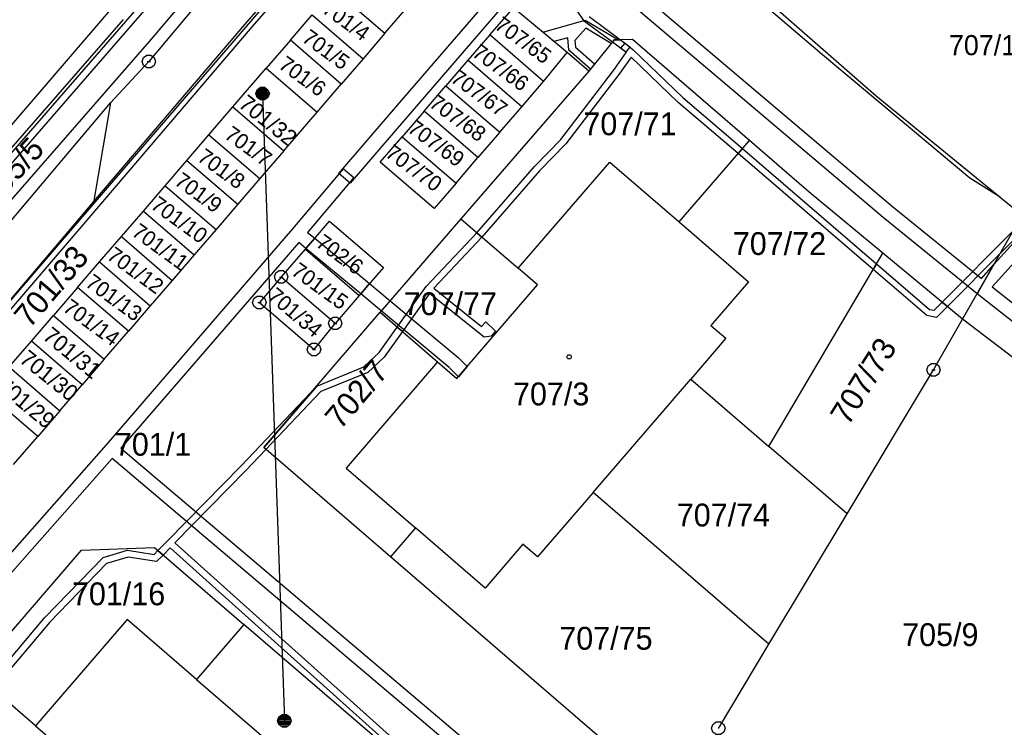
# Model space of a CAD drawing. Extents: x -759060 to -757386, y -1172273 to -1170948.
# Drawn here: x -757830.3 to -757756.9, y -1171110.1 to -1171057.4 of the extents above; entities that cross this region are included whole.
import ezdxf

# ---------------------------------------------------------------- set-up
doc = ezdxf.new("R2010")
doc.units = 0
for name, color, linetype in [('Vrstva 1', 7, 'Continuous'), ('Vrstva 12', 7, 'Continuous'), ('Vrstva 13', 7, 'Continuous'), ('Vrstva 2', 7, 'Continuous'), ('Vrstva 5', 7, 'Continuous'), ('Vrstva 6', 7, 'Continuous'), ('Vrstva 8', 7, 'Continuous')]:
    doc.layers.add(name, color=color, linetype=linetype)

msp = doc.modelspace()

# ---------------------------------------------------------------- linework, layer by layer
at = {"layer": 'Vrstva 1'}
for p, q in [((-757804.36, -1171041.02), (-757820.7, -1171060.56)), ((-757844.19, -1171080.69), (-757811.7, -1171042.9)), ((-757824.84, -1171071.19), (-757804.1, -1171047.12)), ((-757806.89, -1171055.18), (-757803.1, -1171058.44)), ((-757803.1, -1171058.44), (-757801.46, -1171056.55)), ((-757795.29, -1171058.57), (-757793.51, -1171056.55)), ((-757789.52, -1171059.89), (-757793.51, -1171056.55)), ((-757774.02, -1171056.52), (-757766.48, -1171063.11)), ((-757810.15, -1171058.97), (-757808.52, -1171057.07)), ((-757808.52, -1171057.07), (-757804.73, -1171060.34)), ((-757803.1, -1171058.44), (-757804.73, -1171060.34)), ((-757810.15, -1171058.97), (-757811.95, -1171061.05)), ((-757806.37, -1171062.23), (-757810.15, -1171058.97)), ((-757795.29, -1171058.57), (-757796.92, -1171060.46)), ((-757791.28, -1171062.03), (-757795.29, -1171058.57)), ((-757786.02, -1171058.94), (-757787.91, -1171061.26)), ((-757784.66, -1171058.91), (-757786.02, -1171058.94)), ((-757775.94, -1171066.44), (-757784.66, -1171058.91)), ((-757791.28, -1171062.03), (-757789.52, -1171059.89)), ((-757787.91, -1171061.26), (-757789.52, -1171059.89)), ((-757820.7, -1171060.56), (-757823.57, -1171063.62)), ((-757804.73, -1171060.34), (-757806.37, -1171062.23)), ((-757796.92, -1171060.46), (-757798.56, -1171062.36)), ((-757792.91, -1171063.92), (-757796.92, -1171060.46)), ((-757814.43, -1171063.93), (-757811.95, -1171061.05)), ((-757811.95, -1171061.05), (-757808.16, -1171064.31)), ((-757787.91, -1171061.26), (-757797.45, -1171072.26)), ((-757792.91, -1171063.92), (-757791.28, -1171062.03)), ((-757808.16, -1171064.31), (-757806.37, -1171062.23)), ((-757800.18, -1171064.25), (-757798.56, -1171062.36)), ((-757798.56, -1171062.36), (-757794.54, -1171065.82)), ((-757859.93, -1171106.73), (-757823.57, -1171063.62)), ((-757823.57, -1171063.62), (-757824.84, -1171071.19)), ((-757766.48, -1171063.11), (-757755.61, -1171071.99)), ((-757816.22, -1171066.01), (-757814.43, -1171063.93)), ((-757814.43, -1171063.93), (-757810.64, -1171067.19)), ((-757810.64, -1171067.19), (-757808.16, -1171064.31)), ((-757800.18, -1171064.25), (-757801.82, -1171066.15)), ((-757796.17, -1171067.71), (-757800.18, -1171064.25)), ((-757794.54, -1171065.82), (-757792.91, -1171063.92)), ((-757794.54, -1171065.82), (-757796.17, -1171067.71)), ((-757817.86, -1171067.91), (-757816.22, -1171066.01)), ((-757816.22, -1171066.01), (-757812.43, -1171069.27)), ((-757803.45, -1171068.04), (-757801.82, -1171066.15)), ((-757801.82, -1171066.15), (-757797.8, -1171069.6)), ((-757781.18, -1171072.49), (-757775.94, -1171066.44)), ((-757771.48, -1171070.29), (-757775.94, -1171066.44)), ((-757810.64, -1171067.19), (-757812.43, -1171069.27)), ((-757819.48, -1171069.8), (-757817.86, -1171067.91)), ((-757817.86, -1171067.91), (-757814.06, -1171071.17)), ((-757799.43, -1171071.5), (-757803.45, -1171068.04)), ((-757797.8, -1171069.6), (-757796.17, -1171067.71)), ((-757793.17, -1171075.95), (-757786.35, -1171068.04)), ((-757786.35, -1171068.04), (-757781.18, -1171072.49)), ((-757812.43, -1171069.27), (-757814.06, -1171071.17)), ((-757821.11, -1171071.69), (-757819.48, -1171069.8)), ((-757819.48, -1171069.8), (-757815.69, -1171073.06)), ((-757797.8, -1171069.6), (-757799.43, -1171071.5)), ((-757765.99, -1171074.83), (-757771.48, -1171070.29)), ((-757835.44, -1171083.49), (-757824.84, -1171071.19)), ((-757822.75, -1171073.59), (-757821.11, -1171071.69)), ((-757821.11, -1171071.69), (-757817.33, -1171074.96)), ((-757814.06, -1171071.17), (-757815.69, -1171073.06)), ((-757809.03, -1171074.52), (-757807.23, -1171072.43)), ((-757807.23, -1171072.43), (-757803.22, -1171075.89)), ((-757797.45, -1171072.26), (-757803.46, -1171079.23)), ((-757797.45, -1171072.26), (-757793.17, -1171075.95)), ((-757760.04, -1171079.74), (-757755.61, -1171071.99)), ((-757815.69, -1171073.06), (-757817.33, -1171074.96)), ((-757781.18, -1171072.49), (-757775.99, -1171076.96)), ((-757824.38, -1171075.48), (-757822.75, -1171073.59)), ((-757822.75, -1171073.59), (-757818.96, -1171076.85)), ((-757810.83, -1171076.6), (-757809.03, -1171074.52)), ((-757809.03, -1171074.52), (-757805.02, -1171077.98)), ((-757817.33, -1171074.96), (-757818.96, -1171076.85)), ((-757774.48, -1171089.22), (-757765.99, -1171074.83)), ((-757760.04, -1171079.74), (-757765.99, -1171074.83)), ((-757826.01, -1171077.38), (-757824.38, -1171075.48)), ((-757824.38, -1171075.48), (-757820.6, -1171078.75)), ((-757803.22, -1171075.89), (-757805.02, -1171077.98)), ((-757791.73, -1171077.19), (-757793.17, -1171075.95)), ((-757818.96, -1171076.85), (-757820.6, -1171078.75)), ((-757810.83, -1171076.6), (-757812.46, -1171078.5)), ((-757806.81, -1171080.06), (-757810.83, -1171076.6)), ((-757826.01, -1171077.38), (-757827.81, -1171079.46)), ((-757822.22, -1171080.64), (-757826.01, -1171077.38)), ((-757797.74, -1171084.16), (-757791.73, -1171077.19)), ((-757775.99, -1171076.96), (-757778.8, -1171080.22)), ((-757805.02, -1171077.98), (-757806.81, -1171080.06)), ((-757820.6, -1171078.75), (-757822.22, -1171080.64)), ((-757812.46, -1171078.5), (-757808.39, -1171082)), ((-757829.46, -1171081.38), (-757827.81, -1171079.46)), ((-757827.81, -1171079.46), (-757824.02, -1171082.72)), ((-757812.14, -1171089.31), (-757803.46, -1171079.23)), ((-757803.46, -1171079.23), (-757799.18, -1171082.92)), ((-757762.21, -1171083.52), (-757760.04, -1171079.74)), ((-757752.84, -1171085.25), (-757760.04, -1171079.74)), ((-757808.39, -1171082), (-757806.81, -1171080.06)), ((-757778.8, -1171080.22), (-757777.7, -1171081.16)), ((-757824.02, -1171082.72), (-757822.22, -1171080.64)), ((-757777.7, -1171081.16), (-757780.31, -1171084.2)), ((-757831.12, -1171083.3), (-757829.46, -1171081.38)), ((-757825.67, -1171084.64), (-757829.46, -1171081.38)), ((-757824.02, -1171082.72), (-757825.67, -1171084.64)), ((-757831.12, -1171083.3), (-757827.33, -1171086.56)), ((-757799.18, -1171082.92), (-757806, -1171090.84)), ((-757799.18, -1171082.92), (-757797.74, -1171084.16)), ((-757787.59, -1171092.64), (-757780.31, -1171084.2)), ((-757780.31, -1171084.2), (-757774.48, -1171089.22)), ((-757768.64, -1171094.23), (-757762.21, -1171083.52)), ((-757827.33, -1171086.56), (-757825.67, -1171084.64)), ((-757828.98, -1171088.48), (-757832.77, -1171085.22)), ((-757827.33, -1171086.56), (-757828.98, -1171088.48)), ((-757830.78, -1171090.57), (-757828.98, -1171088.48)), ((-757802.69, -1171097.45), (-757812.14, -1171089.31)), ((-757768.64, -1171094.23), (-757774.48, -1171089.22)), ((-757806, -1171090.84), (-757800.83, -1171095.29)), ((-757787.59, -1171092.64), (-757791.73, -1171097.45)), ((-757774.48, -1171103.94), (-757787.59, -1171092.64)), ((-757774.48, -1171103.94), (-757768.64, -1171094.23)), ((-757800.83, -1171095.29), (-757802.69, -1171097.45)), ((-757795.64, -1171099.77), (-757800.83, -1171095.29)), ((-757792.83, -1171096.51), (-757795.64, -1171099.77)), ((-757791.73, -1171097.45), (-757792.83, -1171096.51)), ((-757833.65, -1171106.15), (-757825.72, -1171096.95)), ((-757825.72, -1171096.95), (-757820.27, -1171096.76)), ((-757820.27, -1171096.76), (-757813.62, -1171102.48)), ((-757781.84, -1171115.41), (-757802.69, -1171097.45)), ((-757822.32, -1171102.12), (-757829.14, -1171110.04)), ((-757817.15, -1171106.57), (-757822.32, -1171102.12)), ((-757813.62, -1171102.48), (-757817.15, -1171106.57)), ((-757803.54, -1171111.16), (-757813.62, -1171102.48)), ((-757778.25, -1171110.22), (-757774.48, -1171103.94)), ((-757829.14, -1171110.04), (-757833.65, -1171106.15)), ((-757817.15, -1171106.57), (-757811.96, -1171111.05)), ((-757829.14, -1171110.04), (-757827.7, -1171111.28))]:
    msp.add_line(p, q, dxfattribs=at)
at = {"layer": 'Vrstva 12'}
for p, q in [((-757793.17, -1171075.95), (-757786.35, -1171068.04)), ((-757786.35, -1171068.04), (-757781.18, -1171072.49)), ((-757781.18, -1171072.49), (-757775.99, -1171076.96)), ((-757791.73, -1171077.19), (-757793.17, -1171075.95)), ((-757797.74, -1171084.16), (-757791.73, -1171077.19)), ((-757775.99, -1171076.96), (-757778.8, -1171080.22)), ((-757778.8, -1171080.22), (-757777.7, -1171081.16)), ((-757777.7, -1171081.16), (-757780.31, -1171084.2)), ((-757799.18, -1171082.92), (-757806, -1171090.84)), ((-757799.18, -1171082.92), (-757797.74, -1171084.16)), ((-757787.59, -1171092.64), (-757780.31, -1171084.2)), ((-757806, -1171090.84), (-757800.83, -1171095.29)), ((-757787.59, -1171092.64), (-757791.73, -1171097.45)), ((-757795.64, -1171099.77), (-757800.83, -1171095.29)), ((-757792.83, -1171096.51), (-757795.64, -1171099.77)), ((-757791.73, -1171097.45), (-757792.83, -1171096.51)), ((-757822.32, -1171102.12), (-757829.14, -1171110.04)), ((-757817.15, -1171106.57), (-757822.32, -1171102.12)), ((-757817.15, -1171106.57), (-757811.96, -1171111.05)), ((-757829.14, -1171110.04), (-757827.7, -1171111.28))]:
    msp.add_line(p, q, dxfattribs=at)
at = {"layer": 'Vrstva 13'}
for p, q in [((-757793.28, -1171026.85), (-757820.69, -1171059.05)), ((-757813.39, -1171057.63), (-757804.06, -1171046.81)), ((-757804, -1171047.54), (-757813.01, -1171057.95)), ((-757802.17, -1171063.81), (-757790.75, -1171050.57)), ((-757790.27, -1171051.7), (-757802.35, -1171065.71)), ((-757770.48, -1171060.06), (-757778.23, -1171053.45)), ((-757784.32, -1171055.22), (-757765.27, -1171071.34)), ((-757765.97, -1171072.18), (-757785.02, -1171056.06)), ((-757842.11, -1171080.2), (-757821.43, -1171056.42)), ((-757821.05, -1171056.74), (-757841.71, -1171080.5)), ((-757788.23, -1171057.56), (-757788.8, -1171056.72)), ((-757774.02, -1171056.52), (-757766.48, -1171063.11)), ((-757855.95, -1171095.7), (-757822.59, -1171057.41)), ((-757824.81, -1171070.98), (-757813.39, -1171057.63)), ((-757791.34, -1171058.37), (-757788.18, -1171057.46)), ((-757786.15, -1171059.1), (-757788.23, -1171057.56)), ((-757788.18, -1171057.46), (-757785.69, -1171058.93)), ((-757787.87, -1171057.2), (-757785.54, -1171058.93)), ((-757813.01, -1171057.95), (-757825.9, -1171073.03)), ((-757790.52, -1171059.05), (-757791.34, -1171058.37)), ((-757788.14, -1171058.07), (-757788.94, -1171058.98)), ((-757786.23, -1171059.2), (-757788.14, -1171058.07)), ((-757820.69, -1171059.05), (-757854.07, -1171097.34)), ((-757789.46, -1171058.79), (-757790.52, -1171059.05)), ((-757789.39, -1171059.71), (-757789.46, -1171058.79)), ((-757788.94, -1171058.98), (-757788.91, -1171059.47)), ((-757786.15, -1171059.1), (-757786.23, -1171059.2)), ((-757786.02, -1171058.94), (-757786.15, -1171059.1)), ((-757786.15, -1171059.1), (-757786.02, -1171058.94)), ((-757786.02, -1171058.94), (-757786.15, -1171059.1)), ((-757785.14, -1171059.85), (-757786.15, -1171059.1)), ((-757785.54, -1171058.93), (-757786.02, -1171058.94)), ((-757786.02, -1171058.94), (-757785.54, -1171058.93)), ((-757785.69, -1171058.93), (-757786.02, -1171058.94)), ((-757785.54, -1171058.93), (-757784.84, -1171059.45)), ((-757785.52, -1171059.56), (-757785.2, -1171059.18)), ((-757785.2, -1171059.18), (-757784.63, -1171059.66)), ((-757787.78, -1171061.11), (-757789.39, -1171059.71)), ((-757788.91, -1171059.47), (-757787.47, -1171060.72)), ((-757786, -1171061.12), (-757785.13, -1171059.89)), ((-757785.13, -1171059.89), (-757785.52, -1171059.56)), ((-757784.84, -1171059.45), (-757785.14, -1171059.85)), ((-757784.63, -1171059.66), (-757780.9, -1171063.23)), ((-757784.76, -1171060.23), (-757785.6, -1171061.42)), ((-757781.24, -1171063.59), (-757784.76, -1171060.23)), ((-757759.51, -1171069.25), (-757770.48, -1171060.06)), ((-757790, -1171066.37), (-757786, -1171061.12)), ((-757785.6, -1171061.42), (-757789.62, -1171066.69)), ((-757787.47, -1171060.72), (-757787.78, -1171061.11)), ((-757776.78, -1171067.41), (-757781.24, -1171063.59)), ((-757780.9, -1171063.23), (-757776.46, -1171067.04)), ((-757766.48, -1171063.11), (-757757.24, -1171070.66)), ((-757806.54, -1171068.88), (-757802.17, -1171063.81)), ((-757802.35, -1171065.71), (-757805.7, -1171069.6)), ((-757791.95, -1171068.36), (-757790, -1171066.37)), ((-757789.62, -1171066.69), (-757791.59, -1171068.7)), ((-757776.46, -1171067.04), (-757776.78, -1171067.41)), ((-757776.78, -1171067.41), (-757776.46, -1171067.04)), ((-757776.46, -1171067.04), (-757766.46, -1171075.62)), ((-757766.71, -1171076.05), (-757776.78, -1171067.41)), ((-757809.97, -1171073.01), (-757806.18, -1171068.54)), ((-757806.18, -1171068.54), (-757805.41, -1171069.18)), ((-757796.25, -1171073.3), (-757791.95, -1171068.36)), ((-757791.59, -1171068.7), (-757795.87, -1171073.63)), ((-757805.41, -1171069.18), (-757808.87, -1171073.28)), ((-757805.7, -1171069.6), (-757806.54, -1171068.88)), ((-757757.24, -1171070.66), (-757759.51, -1171069.25)), ((-757826.28, -1171072.71), (-757824.81, -1171070.98)), ((-757765.27, -1171071.34), (-757758.64, -1171076.7)), ((-757758.96, -1171077.86), (-757765.97, -1171072.18)), ((-757825.9, -1171073.03), (-757839.58, -1171088.99)), ((-757835.44, -1171083.49), (-757826.28, -1171072.71)), ((-757823.86, -1171089.09), (-757809.97, -1171073.01)), ((-757761.57, -1171078.48), (-757756.28, -1171073.16)), ((-757754.09, -1171073.18), (-757757.84, -1171077.34)), ((-757757.72, -1171075.68), (-757754.9, -1171072.55)), ((-757755.48, -1171073.06), (-757757.23, -1171074.82)), ((-757808.99, -1171074.47), (-757808.33, -1171073.71)), ((-757808.33, -1171073.71), (-757808.99, -1171074.47)), ((-757808.87, -1171073.28), (-757808.33, -1171073.71)), ((-757808.33, -1171073.71), (-757804.26, -1171077.09)), ((-757800.02, -1171077.3), (-757796.25, -1171073.3)), ((-757795.87, -1171073.63), (-757799.46, -1171077.43)), ((-757795.87, -1171073.63), (-757796.25, -1171073.3)), ((-757796.25, -1171073.3), (-757795.87, -1171073.63)), ((-757809.53, -1171074.04), (-757822.78, -1171089.36)), ((-757808.99, -1171074.47), (-757809.53, -1171074.04)), ((-757804.91, -1171077.86), (-757808.99, -1171074.47)), ((-757757.23, -1171074.82), (-757761.18, -1171078.8)), ((-757766.71, -1171076.05), (-757766.46, -1171075.62)), ((-757766.46, -1171075.62), (-757766.71, -1171076.05)), ((-757762.72, -1171079.47), (-757766.71, -1171076.05)), ((-757766.46, -1171075.62), (-757762.5, -1171079.01)), ((-757757.72, -1171075.68), (-757758.96, -1171077.86)), ((-757758.96, -1171077.86), (-757757.72, -1171075.68)), ((-757758.64, -1171076.7), (-757757.72, -1171075.68)), ((-757804.26, -1171077.09), (-757804.91, -1171077.86)), ((-757804.91, -1171077.86), (-757804.26, -1171077.09)), ((-757804.26, -1171077.09), (-757802.72, -1171078.37)), ((-757802.18, -1171080.33), (-757800.02, -1171077.3)), ((-757799.46, -1171077.43), (-757795.9, -1171080.29)), ((-757757.84, -1171077.34), (-757751.62, -1171082.24)), ((-757803.38, -1171079.13), (-757804.91, -1171077.86)), ((-757799.78, -1171077.82), (-757801.8, -1171080.66)), ((-757795.7, -1171081.09), (-757799.78, -1171077.82)), ((-757752.3, -1171083.1), (-757758.96, -1171077.86)), ((-757802.72, -1171078.37), (-757803.38, -1171079.13)), ((-757803.38, -1171079.13), (-757802.72, -1171078.37)), ((-757802.72, -1171078.37), (-757797.64, -1171082.59)), ((-757762.5, -1171079.01), (-757762.15, -1171079.07)), ((-757762.15, -1171079.07), (-757761.57, -1171078.48)), ((-757761.18, -1171078.8), (-757761.99, -1171079.61)), ((-757761.18, -1171078.8), (-757761.57, -1171078.48)), ((-757761.57, -1171078.48), (-757761.18, -1171078.8)), ((-757798.32, -1171083.33), (-757803.38, -1171079.13)), ((-757761.99, -1171079.61), (-757762.72, -1171079.47)), ((-757803.54, -1171082.23), (-757802.18, -1171080.33)), ((-757802.18, -1171080.33), (-757801.8, -1171080.66)), ((-757801.8, -1171080.66), (-757802.18, -1171080.33)), ((-757795.9, -1171080.29), (-757795.59, -1171079.95)), ((-757795.59, -1171079.95), (-757794.85, -1171080.63)), ((-757801.8, -1171080.66), (-757803.16, -1171082.57)), ((-757795.19, -1171081), (-757795.7, -1171081.09)), ((-757794.85, -1171080.63), (-757795.19, -1171081)), ((-757804.67, -1171083.3), (-757803.54, -1171082.23)), ((-757803.16, -1171082.57), (-757804.39, -1171083.72)), ((-757797.64, -1171082.59), (-757796.97, -1171083.27)), ((-757808.19, -1171084.72), (-757804.67, -1171083.3)), ((-757797.63, -1171084.03), (-757798.32, -1171083.33)), ((-757796.97, -1171083.27), (-757797.63, -1171084.03)), ((-757804.39, -1171083.72), (-757807.89, -1171085.14)), ((-757813.83, -1171090.67), (-757808.19, -1171084.72)), ((-757808.19, -1171084.72), (-757812.14, -1171089.31)), ((-757812.14, -1171089.31), (-757808.19, -1171084.72)), ((-757807.89, -1171085.14), (-757811.98, -1171089.45)), ((-757842.47, -1171110.16), (-757823.86, -1171089.09)), ((-757812.14, -1171089.31), (-757811.98, -1171089.45)), ((-757811.98, -1171089.45), (-757812.14, -1171089.31)), ((-757822.78, -1171089.36), (-757787.72, -1171119.02)), ((-757811.98, -1171089.45), (-757813.47, -1171091.01)), ((-757823.44, -1171090.12), (-757841.38, -1171110.44)), ((-757788.42, -1171119.74), (-757823.44, -1171090.12)), ((-757819.3, -1171096.24), (-757813.83, -1171090.67)), ((-757813.47, -1171091.01), (-757818.76, -1171096.41)), ((-757820.02, -1171096.97), (-757819.3, -1171096.24)), ((-757818.76, -1171096.41), (-757800.94, -1171112.38)), ((-757824.11, -1171097.5), (-757822.29, -1171096.94)), ((-757822.29, -1171096.94), (-757820.3, -1171097.26)), ((-757820.3, -1171097.26), (-757820.02, -1171096.97)), ((-757819.64, -1171097.31), (-757820.12, -1171097.8)), ((-757819.64, -1171097.31), (-757820.02, -1171096.97)), ((-757820.02, -1171096.97), (-757819.64, -1171097.31)), ((-757819.11, -1171096.77), (-757819.64, -1171097.31)), ((-757801.32, -1171112.72), (-757819.11, -1171096.77)), ((-757828.47, -1171101.98), (-757824.11, -1171097.5)), ((-757823.85, -1171097.94), (-757828.09, -1171102.32)), ((-757822.25, -1171097.46), (-757823.85, -1171097.94)), ((-757820.12, -1171097.8), (-757822.25, -1171097.46)), ((-757832.7, -1171106.97), (-757828.47, -1171101.98)), ((-757828.09, -1171102.32), (-757832.32, -1171107.3))]:
    msp.add_line(p, q, dxfattribs=at)
at = {"layer": 'Vrstva 5'}
msp.add_lwpolyline([(-757789.28, -1171082.4), (-757789.19, -1171082.55), (-757789.28, -1171082.7), (-757789.46, -1171082.7), (-757789.55, -1171082.55), (-757789.46, -1171082.4)], close=True, dxfattribs=at)
at = {"layer": 'Vrstva 6'}
msp.add_line((-757812.23, -1171062.95), (-757810.6, -1171109.66), dxfattribs=at)
for points in [[(-757812.38, -1171062.47), (-757812.07, -1171062.47), (-757811.82, -1171062.65), (-757811.72, -1171062.94), (-757811.82, -1171063.23), (-757812.07, -1171063.41), (-757812.38, -1171063.41), (-757812.63, -1171063.23), (-757812.73, -1171062.94), (-757812.63, -1171062.65), (-757812.38, -1171062.47), (-757812.35, -1171062.51), (-757812.11, -1171062.51), (-757811.95, -1171062.59), (-757812.51, -1171062.59), (-757812.59, -1171062.67), (-757811.87, -1171062.67), (-757811.87, -1171062.75), (-757812.59, -1171062.75), (-757812.63, -1171062.83), (-757811.83, -1171062.83), (-757811.79, -1171062.91), (-757812.67, -1171062.91), (-757812.67, -1171062.99), (-757811.79, -1171062.99), (-757811.82, -1171063.07), (-757812.63, -1171063.07), (-757812.62, -1171063.15), (-757811.81, -1171063.15), (-757811.86, -1171063.23), (-757812.58, -1171063.23), (-757812.5, -1171063.31), (-757811.94, -1171063.31), (-757812.05, -1171063.39), (-757812.39, -1171063.39)], [(-757810.75, -1171109.18), (-757810.44, -1171109.18), (-757810.19, -1171109.36), (-757810.09, -1171109.65), (-757810.19, -1171109.94), (-757810.44, -1171110.12), (-757810.75, -1171110.12), (-757811, -1171109.94), (-757811.1, -1171109.65), (-757811, -1171109.36), (-757810.75, -1171109.18), (-757810.72, -1171109.22), (-757810.48, -1171109.22), (-757810.32, -1171109.3), (-757810.88, -1171109.3), (-757810.96, -1171109.38), (-757810.24, -1171109.38), (-757810.24, -1171109.46), (-757810.96, -1171109.46), (-757811, -1171109.54), (-757810.2, -1171109.54), (-757810.16, -1171109.62), (-757811.04, -1171109.62), (-757811.04, -1171109.7), (-757810.16, -1171109.7), (-757810.19, -1171109.78), (-757811, -1171109.78), (-757810.99, -1171109.86), (-757810.18, -1171109.86), (-757810.23, -1171109.94), (-757810.95, -1171109.94), (-757810.87, -1171110.02), (-757810.31, -1171110.02), (-757810.42, -1171110.1), (-757810.76, -1171110.1)]]:
    msp.add_lwpolyline(points, dxfattribs=at)
at = {"layer": 'Vrstva 8'}
for p, q in [((-757820.82, -1171060.56), (-757820.58, -1171060.56)), ((-757810.95, -1171076.6), (-757810.71, -1171076.6)), ((-757812.58, -1171078.5), (-757812.34, -1171078.5)), ((-757806.93, -1171080.06), (-757806.69, -1171080.06)), ((-757808.51, -1171082), (-757808.27, -1171082)), ((-757762.33, -1171083.52), (-757762.09, -1171083.52))]:
    msp.add_line(p, q, dxfattribs=at)
for points in [[(-757820.55, -1171060.08), (-757820.3, -1171060.26), (-757820.2, -1171060.55), (-757820.3, -1171060.84), (-757820.55, -1171061.02), (-757820.86, -1171061.02), (-757821.11, -1171060.84), (-757821.21, -1171060.55), (-757821.11, -1171060.26), (-757820.86, -1171060.08)], [(-757810.68, -1171076.12), (-757810.43, -1171076.3), (-757810.33, -1171076.59), (-757810.43, -1171076.88), (-757810.68, -1171077.06), (-757810.99, -1171077.06), (-757811.24, -1171076.88), (-757811.34, -1171076.59), (-757811.24, -1171076.3), (-757810.99, -1171076.12)], [(-757812.31, -1171078.02), (-757812.06, -1171078.2), (-757811.96, -1171078.49), (-757812.06, -1171078.78), (-757812.31, -1171078.96), (-757812.62, -1171078.96), (-757812.87, -1171078.78), (-757812.97, -1171078.49), (-757812.87, -1171078.2), (-757812.62, -1171078.02)], [(-757806.66, -1171079.58), (-757806.41, -1171079.76), (-757806.31, -1171080.05), (-757806.41, -1171080.34), (-757806.66, -1171080.52), (-757806.97, -1171080.52), (-757807.22, -1171080.34), (-757807.32, -1171080.05), (-757807.22, -1171079.76), (-757806.97, -1171079.58)], [(-757808.24, -1171081.52), (-757807.99, -1171081.7), (-757807.89, -1171081.99), (-757807.99, -1171082.28), (-757808.24, -1171082.46), (-757808.55, -1171082.46), (-757808.8, -1171082.28), (-757808.9, -1171081.99), (-757808.8, -1171081.7), (-757808.55, -1171081.52)], [(-757762.06, -1171083.04), (-757761.81, -1171083.22), (-757761.71, -1171083.51), (-757761.81, -1171083.8), (-757762.06, -1171083.98), (-757762.37, -1171083.98), (-757762.62, -1171083.8), (-757762.72, -1171083.51), (-757762.62, -1171083.22), (-757762.37, -1171083.04)], [(-757778.1, -1171109.74), (-757777.85, -1171109.92), (-757777.75, -1171110.21), (-757777.85, -1171110.5), (-757778.1, -1171110.68), (-757778.41, -1171110.68), (-757778.66, -1171110.5), (-757778.76, -1171110.21), (-757778.66, -1171109.92), (-757778.41, -1171109.74)]]:
    msp.add_lwpolyline(points, close=True, dxfattribs=at)

# ---------------------------------------------------------------- texts
at = {"layer": 'Vrstva 2'}
for s, height, rotation, p in [('701/4', 1.14, 324.00763, (-757807.867, -1171056.839)), ('707/65', 1.14, 324.00763, (-757795.013, -1171058.048)), ('701/5', 1.14, 324.00763, (-757809.372, -1171058.991)), ('707/66', 1.14, 324.00763, (-757796.688, -1171060.087)), ('701/6', 1.14, 324.00763, (-757811.117, -1171060.979)), ('707/67', 1.14, 324.00763, (-757798.286, -1171061.992)), ('701/32', 1.2, 321.31473, (-757814.101, -1171063.868)), ('707/68', 1.14, 324.00763, (-757799.889, -1171063.849)), ('707/69', 1.14, 324.00763, (-757801.498, -1171065.727)), ('701/7', 1.14, 324.00763, (-757815.155, -1171066.195)), ('795/5', 1.7, 47.72738, (-757832.215, -1171071.38)), ('701/8', 1.14, 324.00763, (-757817.168, -1171067.872)), ('707/70', 1.14, 324.00763, (-757803.16, -1171067.572)), ('701/9', 1.14, 324.00763, (-757818.877, -1171069.649)), ('701/10', 1.14, 324.00763, (-757820.646, -1171071.424)), ('701/11', 1.14, 324.00763, (-757822.063, -1171073.442)), ('702/6', 1.14, 324.00763, (-757808.335, -1171074.253)), ('701/33', 1.7, 49.61814, (-757829.589, -1171080.478)), ('701/12', 1.14, 324.00763, (-757823.912, -1171075.196)), ('701/15', 1.14, 324.00763, (-757810.167, -1171076.357)), ('701/13', 1.14, 324.00763, (-757825.519, -1171077.221)), ('701/34', 1.14, 319.59586, (-757811.935, -1171078.157)), ('701/14', 1.14, 324.00763, (-757827.192, -1171079.075)), ('701/31', 1.2, 320.56989, (-757828.7, -1171081.152)), ('707/73', 1.7, 58.09792, (-757768.565, -1171087.744)), ('701/30', 1.2, 321.42932, (-757830.432, -1171082.879)), ('702/7', 1.7, 49.67544, (-757806.415, -1171088.033)), ('701/29', 1.2, 320.398, (-757832.138, -1171084.862))]:
    msp.add_text(s, height=height, rotation=rotation, dxfattribs=at).set_placement(p)
for s, height, p in [('707/17', 1.5, (-757761.065, -1171060.08)), ('707/71', 1.7, (-757788.311, -1171066.04)), ('707/72', 1.7, (-757777.172, -1171074.96)), ('707/77', 1.7, (-757801.709, -1171079.44)), ('707/3', 1.7, (-757793.557, -1171086.16)), ('701/1', 1.7, (-757823.234, -1171089.91)), ('707/74', 1.7, (-757781.349, -1171095.18)), ('701/16', 1.7, (-757826.433, -1171101.05)), ('705/9', 1.7, (-757764.547, -1171104.09)), ('707/75', 1.7, (-757790.106, -1171104.36))]:
    msp.add_text(s, height=height, dxfattribs=at).set_placement(p)

doc.saveas('drawing.dxf')
